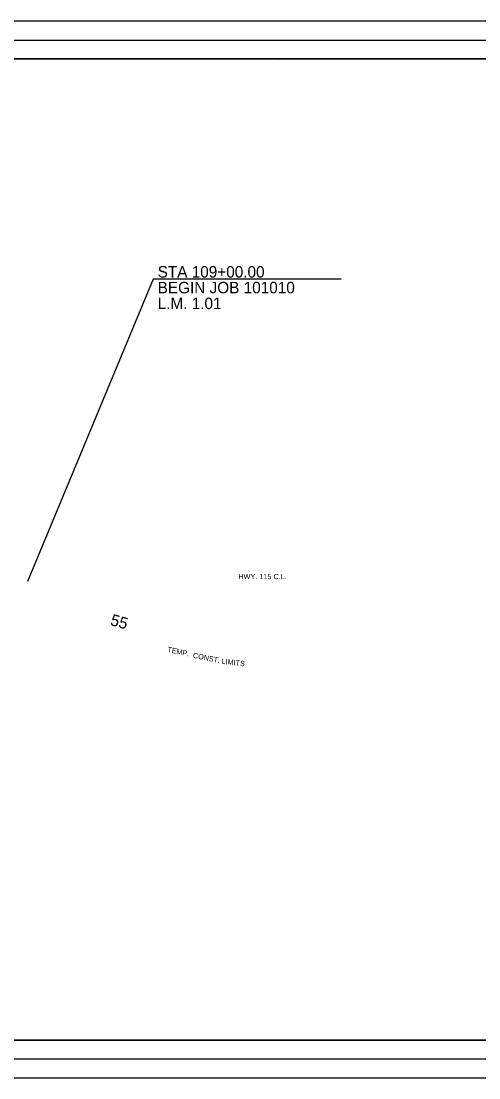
# Model space of a CAD drawing. Extents: x 7675 to 14104, y 9961 to 11168.
# Drawn here: x 8724 to 9203, y 9961 to 11067 of the extents above; entities that cross this region are included whole.
import ezdxf

# ---------------------------------------------------------------- set-up
doc = ezdxf.new("R2010")
doc.units = 0
for name, color, linetype in [('GREEN_TXT', 7, 'Continuous'), ('R_Draft', 7, 'Continuous'), ('S_TREE', 7, 'Continuous'), ('SEAL-INFO', 7, 'Continuous'), ('Stage 1 Construction', 7, 'Continuous'), ('Stage 1 Ditch Checks', 7, 'Continuous'), ('Stage 2 Construction', 7, 'Continuous')]:
    doc.layers.add(name, color=color, linetype=linetype)

msp = doc.modelspace()

# ---------------------------------------------------------------- linework, layer by layer
at = {"layer": 'GREEN_TXT'}
for p, q in [((9834.6, 11066.7), (8074.6, 11066.7)), ((8230.7, 11027.3), (9811.6, 11027.3)), ((8993.3, 11026), (8993.3, 11026)), ((8993.3, 11026), (8993.3, 11026)), ((9811.6, 10000), (8230.7, 10000)), ((8074.6, 9960.6), (9834.6, 9960.6))]:
    msp.add_line(p, q, dxfattribs=at)
at = {"layer": 'SEAL-INFO'}
msp.add_lwpolyline([(8168.6, 11046.8), (9835.3, 11046.8), (9835.3, 9980.1), (8168.6, 9980.1)], close=True, dxfattribs=at)
at = {"layer": 'Stage 1 Construction'}
msp.add_lwpolyline([(9059.2, 10796.7), (8862.2, 10796.7), (8730.7, 10480)], dxfattribs=at)
at = {"layer": 'Stage 1 Ditch Checks'}
msp.add_lwpolyline([(8230.7, 10000), (9811.6, 10000), (9811, 10963.3), (9596.1, 10963.3), (9588, 10959.9), (9579.2, 10961.4), (9578.9, 10977.9), (9400.3, 10977.9), (9400.3, 11027.3), (8230.7, 11027.3)], close=True, dxfattribs=at)
msp.add_lwpolyline([(8230.7, 10000), (9811.6, 10000), (9811, 10963.3), (9596.1, 10963.3), (9588, 10959.9), (9579.2, 10961.4), (9578.9, 10977.9), (9400.3, 10977.9), (9400.3, 11027.3), (8230.7, 11027.3)], close=True, dxfattribs=at)
msp.add_lwpolyline([(8230.7, 10000), (9811.6, 10000), (9811, 10963.3), (9596.1, 10963.3), (9588, 10959.9), (9579.2, 10961.4), (9578.9, 10977.9), (9400.3, 10977.9), (9400.3, 11027.3), (8230.7, 11027.3)], close=True, dxfattribs=at)
msp.add_lwpolyline([(8230.7, 10000), (9811.6, 10000), (9811, 10963.3), (9596.1, 10963.3), (9588, 10959.9), (9579.2, 10961.4), (9578.9, 10977.9), (9400.3, 10977.9), (9400.3, 11027.3), (8230.7, 11027.3)], close=True, dxfattribs=at)
msp.add_lwpolyline([(8230.7, 10000), (9811.6, 10000), (9811, 10963.3), (9596.1, 10963.3), (9588, 10959.9), (9579.2, 10961.4), (9578.9, 10977.9), (9400.3, 10977.9), (9400.3, 11027.3), (8230.7, 11027.3)], close=True, dxfattribs=at)

# ---------------------------------------------------------------- texts
at = {"layer": 'R_Draft'}
msp.add_text('55', height=12, rotation=343.9098, dxfattribs=at).set_placement((8816.7, 10434.8))
at = {"layer": 'S_TREE'}
msp.add_text('HWY. 115 C.L.', height=5.5, dxfattribs=at).set_placement((8951.5, 10482.6))
at = {"layer": 'Stage 1 Construction'}
for s, p in [('STA 109+00.00', (8867, 10798.3)), ('BEGIN JOB 101010', (8867, 10781.8)), ('L.M. 1.01', (8867, 10765.3))]:
    msp.add_text(s, height=12, dxfattribs=at).set_placement(p)
at = {"layer": 'Stage 2 Construction'}
for s, rotation, p in [('TEMP. ', 348.2225, (8876.8, 10406.5)), ('CONST. ', 348.7283, (8903.6, 10400.4)), (' LIMITS', 353.3192, (8931.5, 10394.4))]:
    msp.add_text(s, height=5.5, rotation=rotation, dxfattribs=at).set_placement(p)

doc.saveas('drawing.dxf')
